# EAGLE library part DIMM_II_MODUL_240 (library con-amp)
DDR2 DIMM Socket Source: http://pinouts.ru/Memory/dimm_ddr2_pinout.shtml Auto generated by make-symbol-device-package-bsdl.ulp Rev. 20
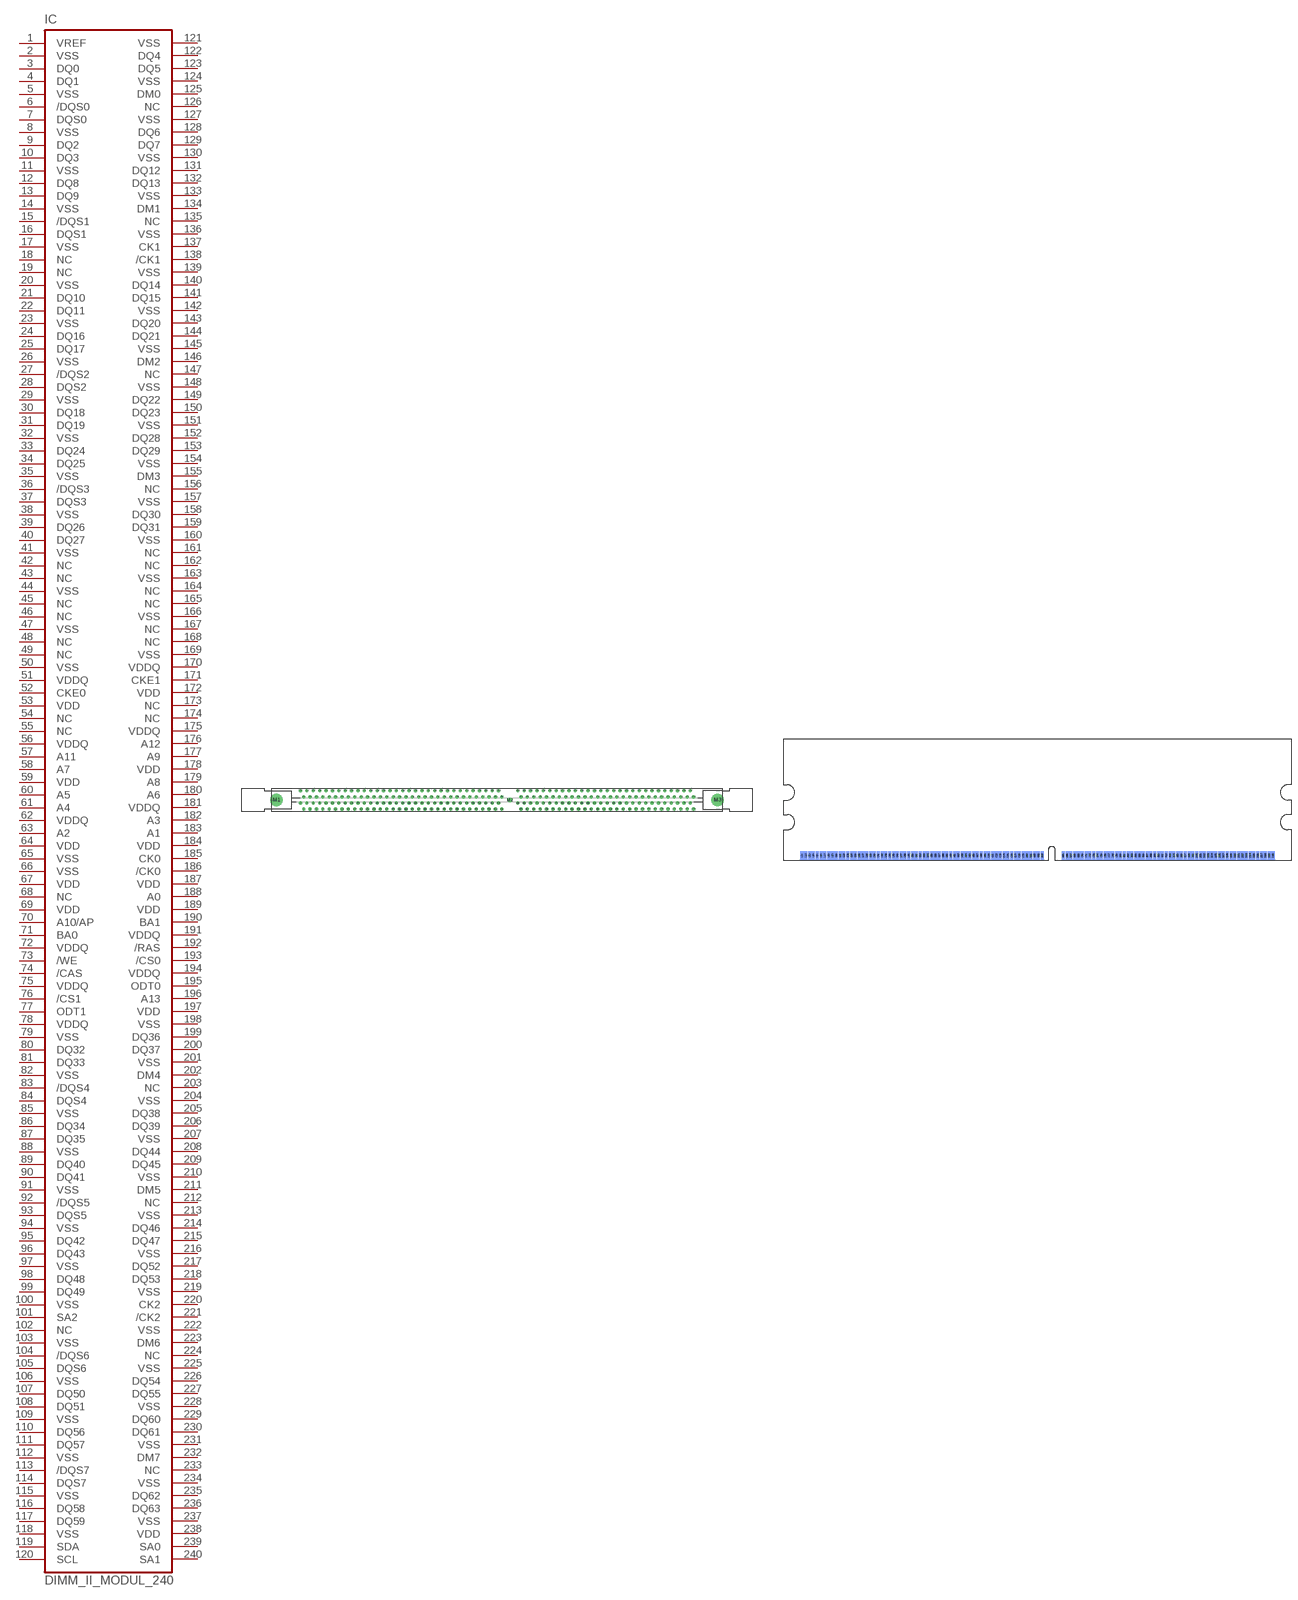
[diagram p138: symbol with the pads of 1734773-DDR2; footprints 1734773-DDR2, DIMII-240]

Designator prefix IC

## DIMM_II_MODUL_240 (OC_FARNELL: unknown; OC_NEWARK: unknown)  [1734773-DDR2]
1  VREF  pas
2  VSS  pas
3  DQ0  pas
4  DQ1  pas
5  VSS  pas
6  /DQS0  pas
7  DQS0  pas
8  VSS  pas
9  DQ2  pas
10  DQ3  pas
11  VSS  pas
12  DQ8  pas
13  DQ9  pas
14  VSS  pas
15  /DQS1  pas
16  DQS1  pas
17  VSS  pas
18  NC  pas
19  NC  pas
20  VSS  pas
21  DQ10  pas
22  DQ11  pas
23  VSS  pas
24  DQ16  pas
25  DQ17  pas
26  VSS  pas
27  /DQS2  pas
28  DQS2  pas
29  VSS  pas
30  DQ18  pas
31  DQ19  pas
32  VSS  pas
33  DQ24  pas
34  DQ25  pas
35  VSS  pas
36  /DQS3  pas
37  DQS3  pas
38  VSS  pas
39  DQ26  pas
40  DQ27  pas
41  VSS  pas
42  NC  pas
43  NC  pas
44  VSS  pas
45  NC  pas
46  NC  pas
47  VSS  pas
48  NC  pas
49  NC  pas
50  VSS  pas
51  VDDQ  pas
52  CKE0  pas
53  VDD  pas
54  NC  pas
55  NC  pas
56  VDDQ  pas
57  A11  pas
58  A7  pas
59  VDD  pas
60  A5  pas
61  A4  pas
62  VDDQ  pas
63  A2  pas
64  VDD  pas
65  VSS  pas
66  VSS  pas
67  VDD  pas
68  NC  pas
69  VDD  pas
70  A10/AP  pas
71  BA0  pas
72  VDDQ  pas
73  /WE  pas
74  /CAS  pas
75  VDDQ  pas
76  /CS1  pas
77  ODT1  pas
78  VDDQ  pas
79  VSS  pas
80  DQ32  pas
81  DQ33  pas
82  VSS  pas
83  /DQS4  pas
84  DQS4  pas
85  VSS  pas
86  DQ34  pas
87  DQ35  pas
88  VSS  pas
89  DQ40  pas
90  DQ41  pas
91  VSS  pas
92  /DQS5  pas
93  DQS5  pas
94  VSS  pas
95  DQ42  pas
96  DQ43  pas
97  VSS  pas
98  DQ48  pas
99  DQ49  pas
100  VSS  pas
101  SA2  pas
102  NC  pas
103  VSS  pas
104  /DQS6  pas
105  DQS6  pas
106  VSS  pas
107  DQ50  pas
108  DQ51  pas
109  VSS  pas
110  DQ56  pas
111  DQ57  pas
112  VSS  pas
113  /DQS7  pas
114  DQS7  pas
115  VSS  pas
116  DQ58  pas
117  DQ59  pas
118  VSS  pas
119  SDA  pas
120  SCL  pas
121  VSS  pas
122  DQ4  pas
123  DQ5  pas
124  VSS  pas
125  DM0  pas
126  NC  pas
127  VSS  pas
128  DQ6  pas
129  DQ7  pas
130  VSS  pas
131  DQ12  pas
132  DQ13  pas
133  VSS  pas
134  DM1  pas
135  NC  pas
136  VSS  pas
137  CK1  pas
138  /CK1  pas
139  VSS  pas
140  DQ14  pas
141  DQ15  pas
142  VSS  pas
143  DQ20  pas
144  DQ21  pas
145  VSS  pas
146  DM2  pas
147  NC  pas
148  VSS  pas
149  DQ22  pas
150  DQ23  pas
151  VSS  pas
152  DQ28  pas
153  DQ29  pas
154  VSS  pas
155  DM3  pas
156  NC  pas
157  VSS  pas
158  DQ30  pas
159  DQ31  pas
160  VSS  pas
161  NC  pas
162  NC  pas
163  VSS  pas
164  NC  pas
165  NC  pas
166  VSS  pas
167  NC  pas
168  NC  pas
169  VSS  pas
170  VDDQ  pas
171  CKE1  pas
172  VDD  pas
173  NC  pas
174  NC  pas
175  VDDQ  pas
176  A12  pas
177  A9  pas
178  VDD  pas
179  A8  pas
180  A6  pas
181  VDDQ  pas
182  A3  pas
183  A1  pas
184  VDD  pas
185  CK0  pas
186  /CK0  pas
187  VDD  pas
188  A0  pas
189  VDD  pas
190  BA1  pas
191  VDDQ  pas
192  /RAS  pas
193  /CS0  pas
194  VDDQ  pas
195  ODT0  pas
196  A13  pas
197  VDD  pas
198  VSS  pas
199  DQ36  pas
200  DQ37  pas
201  VSS  pas
202  DM4  pas
203  NC  pas
204  VSS  pas
205  DQ38  pas
206  DQ39  pas
207  VSS  pas
208  DQ44  pas
209  DQ45  pas
210  VSS  pas
211  DM5  pas
212  NC  pas
213  VSS  pas
214  DQ46  pas
215  DQ47  pas
216  VSS  pas
217  DQ52  pas
218  DQ53  pas
219  VSS  pas
220  CK2  pas
221  /CK2  pas
222  VSS  pas
223  DM6  pas
224  NC  pas
225  VSS  pas
226  DQ54  pas
227  DQ55  pas
228  VSS  pas
229  DQ60  pas
230  DQ61  pas
231  VSS  pas
232  DM7  pas
233  NC  pas
234  VSS  pas
235  DQ62  pas
236  DQ63  pas
237  VSS  pas
238  VDD  pas
239  SA0  pas
240  SA1  pas

## DIMM_II_MODUL_240-CARD (MPN: 1775802-1; OC_FARNELL: 1326665; OC_NEWARK: 10M7282)  [DIMII-240]
Pads as for 1734773-DDR2

## Footprint 1734773-DDR2 (pad centres in mm)
DIMM II (DDR II) 240 Pin Connector Source: http://catalog.tycoelectronics.com .. ENG_CD_1734773_B.tif
drill 0.5 pad 0.9 round: 1 -64.5,-2.85; 2 -65.5,-0.95; 3 -62.5,-2.85; 4 -63.5,-0.95; 5 -60.5,-2.85; 6 -61.5,-0.95; 7 -58.5,-2.85; 8 -59.5,-0.95; 9 -56.5,-2.85; 10 -57.5,-0.95; 11 -54.5,-2.85; 12 -55.5,-0.95; 13 -52.5,-2.85; 14 -53.5,-0.95; 15 -50.5,-2.85; 16 -51.5,-0.95; 17 -48.5,-2.85; 18 -49.5,-0.95; 19 -46.5,-2.85; 20 -47.5,-0.95; 21 -44.5,-2.85; 22 -45.5,-0.95; 23 -42.5,-2.85; 24 -43.5,-0.95; 25 -40.5,-2.85; 26 -41.5,-0.95; 27 -38.5,-2.85; 28 -39.5,-0.95; 29 -36.5,-2.85; 30 -37.5,-0.95; 31 -34.5,-2.85; 32 -35.5,-0.95; 33 -32.5,-2.85; 34 -33.5,-0.95; 35 -30.5,-2.85; 36 -31.5,-0.95; 37 -28.5,-2.85; 38 -29.5,-0.95; 39 -26.5,-2.85; 40 -27.5,-0.95; 41 -24.5,-2.85; 42 -25.5,-0.95; 43 -22.5,-2.85; 44 -23.5,-0.95; 45 -20.5,-2.85; 46 -21.5,-0.95; 47 -18.5,-2.85; 48 -19.5,-0.95; 49 -16.5,-2.85; 50 -17.5,-0.95; 51 -14.5,-2.85; 52 -15.5,-0.95; 53 -12.5,-2.85; 54 -13.5,-0.95; 55 -10.5,-2.85; 56 -11.5,-0.95; 57 -8.5,-2.85; 58 -9.5,-0.95; 59 -6.5,-2.85; 60 -7.5,-0.95; 61 -4.5,-2.85; 62 -5.5,-0.95; 63 -2.5,-2.85; 64 -3.5,-0.95; 65 3.5,-2.85; 66 2.5,-0.95; 67 5.5,-2.85; 68 4.5,-0.95; 69 7.5,-2.85; 70 6.5,-0.95; 71 9.5,-2.85; 72 8.5,-0.95; 73 11.5,-2.85; 74 10.5,-0.95; 75 13.5,-2.85; 76 12.5,-0.95; 77 15.5,-2.85; 78 14.5,-0.95; 79 17.5,-2.85; 80 16.5,-0.95; 81 19.5,-2.85; 82 18.5,-0.95; 83 21.5,-2.85; 84 20.5,-0.95; 85 23.5,-2.85; 86 22.5,-0.95; 87 25.5,-2.85; 88 24.5,-0.95; 89 27.5,-2.85; 90 26.5,-0.95; 91 29.5,-2.85; 92 28.5,-0.95; 93 31.5,-2.85; 94 30.5,-0.95; 95 33.5,-2.85; 96 32.5,-0.95; 97 35.5,-2.85; 98 34.5,-0.95; 99 37.5,-2.85; 100 36.5,-0.95; 101 39.5,-2.85; 102 38.5,-0.95; 103 41.5,-2.85; 104 40.5,-0.95; 105 43.5,-2.85; 106 42.5,-0.95; 107 45.5,-2.85; 108 44.5,-0.95; 109 47.5,-2.85; 110 46.5,-0.95; 111 49.5,-2.85; 112 48.5,-0.95; 113 51.5,-2.85; 114 50.5,-0.95; 115 53.5,-2.85; 116 52.5,-0.95; 117 55.5,-2.85; 118 54.5,-0.95; 119 57.5,-2.85; 120 56.5,-0.95; 121 -64.5,0.95; 122 -65.5,2.85; 123 -62.5,0.95; 124 -63.5,2.85; 125 -60.5,0.95; 126 -61.5,2.85; 127 -58.5,0.95; 128 -59.5,2.85; 129 -56.5,0.95; 130 -57.5,2.85; 131 -54.5,0.95; 132 -55.5,2.85; 133 -52.5,0.95; 134 -53.5,2.85; 135 -50.5,0.95; 136 -51.5,2.85; 137 -48.5,0.95; 138 -49.5,2.85; 139 -46.5,0.95; 140 -47.5,2.85; 141 -44.5,0.95; 142 -45.5,2.85; 143 -42.5,0.95; 144 -43.5,2.85; 145 -40.5,0.95; 146 -41.5,2.85; 147 -38.5,0.95; 148 -39.5,2.85; 149 -36.5,0.95; 150 -37.5,2.85; 151 -34.5,0.95; 152 -35.5,2.85; 153 -32.5,0.95; 154 -33.5,2.85; 155 -30.5,0.95; 156 -31.5,2.85; 157 -28.5,0.95; 158 -29.5,2.85; 159 -26.5,0.95; 160 -27.5,2.85; 161 -24.5,0.95; 162 -25.5,2.85; 163 -22.5,0.95; 164 -23.5,2.85; 165 -20.5,0.95; 166 -21.5,2.85; 167 -18.5,0.95; 168 -19.5,2.85; 169 -16.5,0.95; 170 -17.5,2.85; 171 -14.5,0.95; 172 -15.5,2.85; 173 -12.5,0.95; 174 -13.5,2.85; 175 -10.5,0.95; 176 -11.5,2.85; 177 -8.5,0.95; 178 -9.5,2.85; 179 -6.5,0.95; 180 -7.5,2.85; 181 -4.5,0.95; 182 -5.5,2.85; 183 -2.5,0.95; 184 -3.5,2.85; 185 3.5,0.95; 186 2.5,2.85; 187 5.5,0.95; 188 4.5,2.85; 189 7.5,0.95; 190 6.5,2.85; 191 9.5,0.95; 192 8.5,2.85; 193 11.5,0.95; 194 10.5,2.85; 195 13.5,0.95; 196 12.5,2.85; 197 15.5,0.95; 198 14.5,2.85; 199 17.5,0.95; 200 16.5,2.85; 201 19.5,0.95; 202 18.5,2.85; 203 21.5,0.95; 204 20.5,2.85; 205 23.5,0.95; 206 22.5,2.85; 207 25.5,0.95; 208 24.5,2.85; 209 27.5,0.95; 210 26.5,2.85; 211 29.5,0.95; 212 28.5,2.85; 213 31.5,0.95; 214 30.5,2.85; 215 33.5,0.95; 216 32.5,2.85; 217 35.5,0.95; 218 34.5,2.85; 219 37.5,0.95; 220 36.5,2.85; 221 39.5,0.95; 222 38.5,2.85; 223 41.5,0.95; 224 40.5,2.85; 225 43.5,0.95; 226 42.5,2.85; 227 45.5,0.95; 228 44.5,2.85; 229 47.5,0.95; 230 46.5,2.85; 231 49.5,0.95; 232 48.5,2.85; 233 51.5,0.95; 234 50.5,2.85; 235 53.5,0.95; 236 52.5,2.85; 237 55.5,0.95; 238 54.5,2.85; 239 57.5,0.95; 240 56.5,2.85
drill 2.8 pad 3.81 round: M1 -73,0; M3 65,0
drill 0.8 pad 1.5 round: M2 0,0

## Footprint DIMII-240 (pad centres in mm)
DIMM MODUL 240 Pol. DDR2 Source: http://www.ortodoxism.ro/datasheets/infineon/1-DS_512M_T11_ubu_v0.84.pdf'
smd 0.8 x 2.3: 1 -65.5,1.25; 2 -64.5,1.25; 3 -63.5,1.25; 4 -62.5,1.25; 5 -61.5,1.25; 6 -60.5,1.25; 7 -59.5,1.25; 8 -58.5,1.25; 9 -57.5,1.25; 10 -56.5,1.25; 11 -55.5,1.25; 12 -54.5,1.25; 13 -53.5,1.25; 14 -52.5,1.25; 15 -51.5,1.25; 16 -50.5,1.25; 17 -49.5,1.25; 18 -48.5,1.25; 19 -47.5,1.25; 20 -46.5,1.25; 21 -45.5,1.25; 22 -44.5,1.25; 23 -43.5,1.25; 24 -42.5,1.25; 25 -41.5,1.25; 26 -40.5,1.25; 27 -39.5,1.25; 28 -38.5,1.25; 29 -37.5,1.25; 30 -36.5,1.25; 31 -35.5,1.25; 32 -34.5,1.25; 33 -33.5,1.25; 34 -32.5,1.25; 35 -31.5,1.25; 36 -30.5,1.25; 37 -29.5,1.25; 38 -28.5,1.25; 39 -27.5,1.25; 40 -26.5,1.25; 41 -25.5,1.25; 42 -24.5,1.25; 43 -23.5,1.25; 44 -22.5,1.25; 45 -21.5,1.25; 46 -20.5,1.25; 47 -19.5,1.25; 48 -18.5,1.25; 49 -17.5,1.25; 50 -16.5,1.25; 51 -15.5,1.25; 52 -14.5,1.25; 53 -13.5,1.25; 54 -12.5,1.25; 55 -11.5,1.25; 56 -10.5,1.25; 57 -9.5,1.25; 58 -8.5,1.25; 59 -7.5,1.25; 60 -6.5,1.25; 61 -5.5,1.25; 62 -4.5,1.25; 63 -3.5,1.25; 64 -2.5,1.25; 65 3,1.25; 66 4,1.25; 67 5,1.25; 68 6,1.25; 69 7,1.25; 70 8,1.25; 71 9,1.25; 72 10,1.25; 73 11,1.25; 74 12,1.25; 75 13,1.25; 76 14,1.25; 77 15,1.25; 78 16,1.25; 79 17,1.25; 80 18,1.25; 81 19,1.25; 82 20,1.25; 83 21,1.25; 84 22,1.25; 85 23,1.25; 86 24,1.25; 87 25,1.25; 88 26,1.25; 89 27,1.25; 90 28,1.25; 91 29,1.25; 92 30,1.25; 93 31,1.25; 94 32,1.25; 95 33,1.25; 96 34,1.25; 97 35,1.25; 98 36,1.25; 99 37,1.25; 100 38,1.25; 101 39,1.25; 102 40,1.25; 103 41,1.25; 104 42,1.25; 105 43,1.25; 106 44,1.25; 107 45,1.25; 108 46,1.25; 109 47,1.25; 110 48,1.25; 111 49,1.25; 112 50,1.25; 113 51,1.25; 114 52,1.25; 115 53,1.25; 116 54,1.25; 117 55,1.25; 118 56,1.25; 119 57,1.25; 120 58,1.25
smd 0.8 x 2.3 bottom: 121 -65.5,1.25; 122 -64.5,1.25; 123 -63.5,1.25; 124 -62.5,1.25; 125 -61.5,1.25; 126 -60.5,1.25; 127 -59.5,1.25; 128 -58.5,1.25; 129 -57.5,1.25; 130 -56.5,1.25; 131 -55.5,1.25; 132 -54.5,1.25; 133 -53.5,1.25; 134 -52.5,1.25; 135 -51.5,1.25; 136 -50.5,1.25; 137 -49.5,1.25; 138 -48.5,1.25; 139 -47.5,1.25; 140 -46.5,1.25; 141 -45.5,1.25; 142 -44.5,1.25; 143 -43.5,1.25; 144 -42.5,1.25; 145 -41.5,1.25; 146 -40.5,1.25; 147 -39.5,1.25; 148 -38.5,1.25; 149 -37.5,1.25; 150 -36.5,1.25; 151 -35.5,1.25; 152 -34.5,1.25; 153 -33.5,1.25; 154 -32.5,1.25; 155 -31.5,1.25; 156 -30.5,1.25; 157 -29.5,1.25; 158 -28.5,1.25; 159 -27.5,1.25; 160 -26.5,1.25; 161 -25.5,1.25; 162 -24.5,1.25; 163 -23.5,1.25; 164 -22.5,1.25; 165 -21.5,1.25; 166 -20.5,1.25; 167 -19.5,1.25; 168 -18.5,1.25; 169 -17.5,1.25; 170 -16.5,1.25; 171 -15.5,1.25; 172 -14.5,1.25; 173 -13.5,1.25; 174 -12.5,1.25; 175 -11.5,1.25; 176 -10.5,1.25; 177 -9.5,1.25; 178 -8.5,1.25; 179 -7.5,1.25; 180 -6.5,1.25; 181 -5.5,1.25; 182 -4.5,1.25; 183 -3.5,1.25; 184 -2.5,1.25; 185 3,1.25; 186 4,1.25; 187 5,1.25; 188 6,1.25; 189 7,1.25; 190 8,1.25; 191 9,1.25; 192 10,1.25; 193 11,1.25; 194 12,1.25; 195 13,1.25; 196 14,1.25; 197 15,1.25; 198 16,1.25; 199 17,1.25; 200 18,1.25; 201 19,1.25; 202 20,1.25; 203 21,1.25; 204 22,1.25; 205 23,1.25; 206 24,1.25; 207 25,1.25; 208 26,1.25; 209 27,1.25; 210 28,1.25; 211 29,1.25; 212 30,1.25; 213 31,1.25; 214 32,1.25; 215 33,1.25; 216 34,1.25; 217 35,1.25; 218 36,1.25; 219 37,1.25; 220 38,1.25; 221 39,1.25; 222 40,1.25; 223 41,1.25; 224 42,1.25; 225 43,1.25; 226 44,1.25; 227 45,1.25; 228 46,1.25; 229 47,1.25; 230 48,1.25; 231 49,1.25; 232 50,1.25; 233 51,1.25; 234 52,1.25; 235 53,1.25; 236 54,1.25; 237 55,1.25; 238 56,1.25; 239 57,1.25; 240 58,1.25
